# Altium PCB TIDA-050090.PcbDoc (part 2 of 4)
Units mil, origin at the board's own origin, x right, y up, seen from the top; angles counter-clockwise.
Board outline 4150 x 4140 mil, 8 copper layers (Top Layer 1, POWER1, GND1, SIGNAL1, SIGNAL2, GND2, POWER2, Bottom Layer 1), stack 60.703 mil thick; 130 components, 39 nets, 355 pads, 2292 vias.
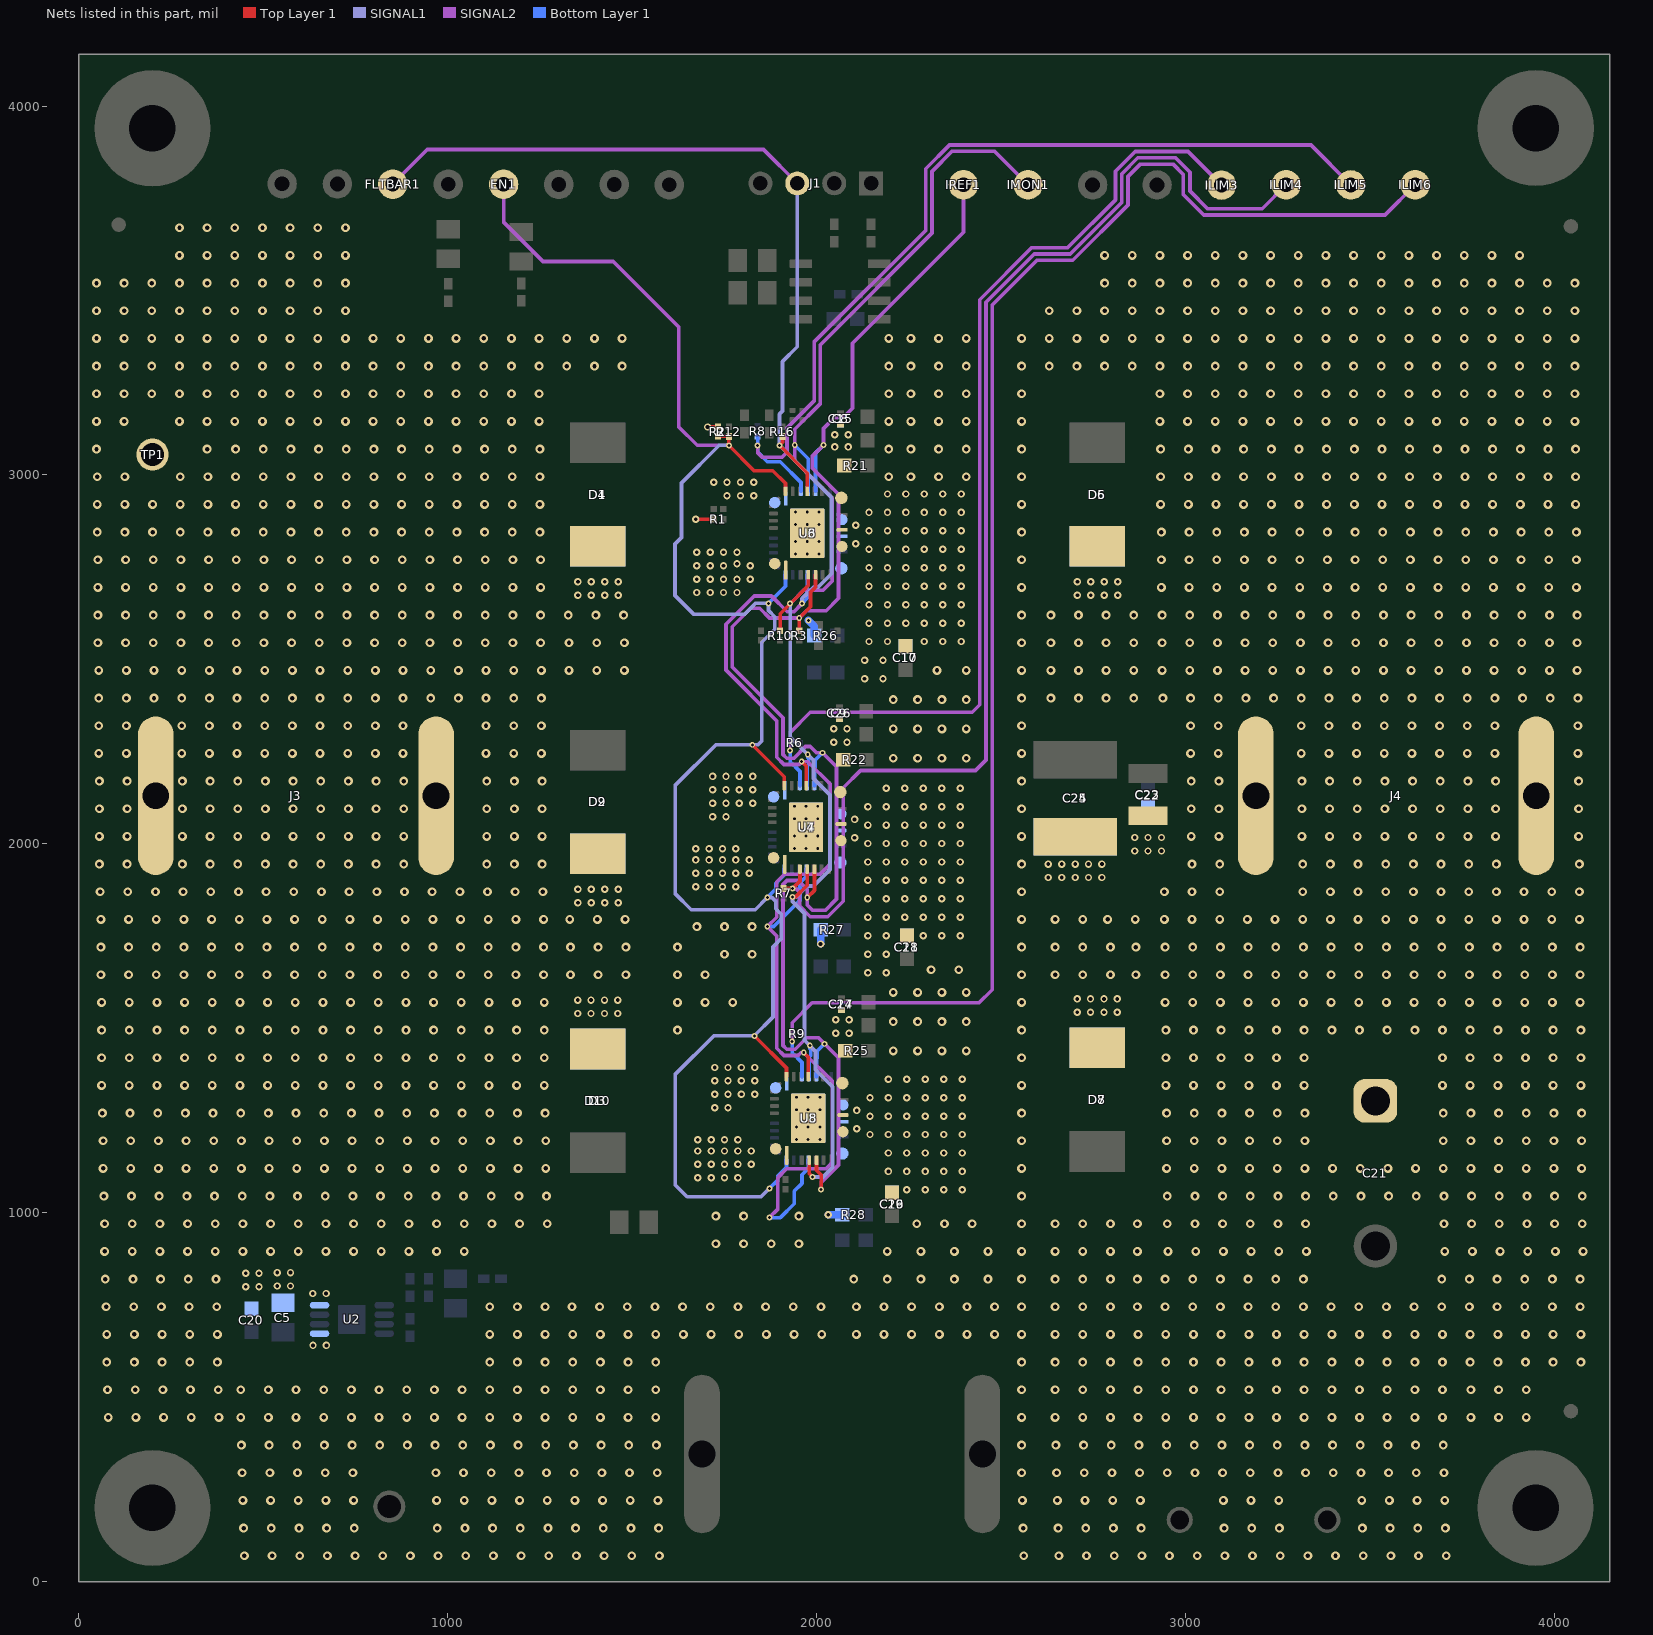
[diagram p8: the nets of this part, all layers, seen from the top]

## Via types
v1: diameter 24, hole 12, Top Layer 1 to Bottom Layer 1, tented both sides, 1740 vias
v2: diameter 20, hole 10, Top Layer 1 to Bottom Layer 1, tented both sides, 444 vias
v3: diameter 16, hole 8, Top Layer 1 to Bottom Layer 1, tented both sides, 67 vias
v4: diameter 19.68, hole 7.87, Top Layer 1 to Bottom Layer 1, tented both sides, 41 vias

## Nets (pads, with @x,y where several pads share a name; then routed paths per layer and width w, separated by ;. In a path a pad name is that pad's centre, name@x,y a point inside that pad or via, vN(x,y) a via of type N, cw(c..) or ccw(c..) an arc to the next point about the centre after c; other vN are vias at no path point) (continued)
Efuse3_ILIM: ILIM3.1 R6.2 U7.1 | length 2723.4
  SIGNAL2 w10: v3(1928.76,2253.39) 1928.76,2302.07 1983.22,2356.53 2422.01,2356.53 2442.44,2376.97 2442.44,3475.39 2583.18,3616.13 2680.82,3616.13 2810.48,3745.79 2810.48,3823.16 2864.07,3876.75 3007.38,3876.75 ILIM3.1@3098.2,3785.94
  Bottom Layer 1 w10: R6.2@1928.76,2273.8 v3(1928.76,2253.39) 1928.76,2222.98 1955.33,2196.4 U7.1@1955.33,2158.19
Efuse4_ILIM: ILIM4.1 R7.2 U4.1 | length 3395.5
  Top Layer 1 w10: R7.2@1911.02,1879.1 v3(1934.93,1879.1) 1955.32,1899.48 U4.1@1955.32,1931.81
  SIGNAL2 w10: v3(1934.93,1879.1) 1944.65,1879.1 1953.93,1869.82 1953.93,1831.64 1982.89,1802.68 2030.63,1802.68 2072.51,1844.56 2072.51,2151.88 2119.68,2199.05 2431.09,2199.05 2459.44,2227.4 2459.44,3468.35 2590.22,3599.13 2687.87,3599.13 2827.48,3738.74 2827.48,3816.12 2871.11,3859.75 2973.32,3859.75 3012.51,3820.57 3012.51,3769.62 3060.17,3721.96 3208.38,3721.96 ILIM4.1@3273.19,3786.77
Efuse5_ILIM: ILIM5.1 R8.2 U6.1 | length 2477.2
  SIGNAL2 w10: v3(1840.51,3080) 1840.51,3061.07 1853.84,3047.73 1906,3047.73 1920.04,3061.77 1920.04,3127.17 1993.63,3200.76 1993.63,3360.44 2295.98,3662.79 2295.98,3830.11 2360.32,3894.45 3340.45,3894.45 ILIM5.1@3448.63,3786.27
  Bottom Layer 1 w10: R8.2@1840.51,3105.46 v3(1840.51,3080) 1840.51,3062.1 1866.65,3035.96 1901.93,3035.96 1958.27,2979.63 U6.1@1958.27,2955.69
Efuse6_ILIM: ILIM6.1 R9.2 U8.1 | length 4085.8
  SIGNAL2 w10: v3(1934.31,1464.45) 1934.31,1515.26 1988.18,1569.13 2440.94,1569.13 2476.44,1604.64 2476.44,3461.06 2597.52,3582.13 2694.91,3582.13 2844.48,3731.7 2844.48,3809.08 2878.15,3842.75 2966.28,3842.75 2993.94,3815.1 2993.94,3761.11 3050.1,3704.96 3541.38,3704.96 ILIM6.1@3623.19,3786.77
  Bottom Layer 1 w10: R9.2@1934.31,1484.86 v3(1934.31,1464.45) 1934.31,1434.04 1960.88,1407.46 U8.1@1960.88,1369.24
Efuse_IN: C5.1 C8.2 C9.2 C14.2 C15.2 C20.1 C26.2 C27.2 D1.1 D2.1 D3.1 D4.1 D9.1 D10.1 J3.1 R1.2 R2.2 R21.2 R22.2 R25.2 R26.2 R27.2 R28.2 TP1.1 U2.5 U2.8 U3.10 U3.22 U3.23 U3.24 U4.10 U4.22 U4.23 U4.24 U5.10 U5.22 U5.23 U5.24 U6.10 U6.22 U6.23 U6.24 U7.10 U7.22 U7.23 U7.24 U8.10 U8.22 U8.23 U8.24 | length 201.7
  Top Layer 1 w10: v2(1672.49,2879.9) R1.2@1721.29,2879.9 ; v2@1704.48,3130.62 R2.2@1732.86,3130.62
  Bottom Layer 1 w20: v3(1977.95,2606.1) 1993.7,2590.36 R26.2@1993.7,2564.86 ; v2(2011.16,1728.61) R27.2@2011.16,1766.96 ; v2(2031.78,994.48) R28.2@2070.13,994.48
  other v1: 449.21,70.29 524.21,70.29 599.21,70.29 674.21,70.29 749.21,70.29 824.21,70.29 899.21,70.29 974.21,70.29 1049.22,70.29 1124.22,70.29 1199.22,70.29 1274.22,70.29 1349.22,70.29 1424.22,70.29 1499.22,70.29 1574.22,70.29 447.21,145.29 522.21,145.29 597.21,145.29 672.21,145.29 747.21,145.29 972.22,145.29 1047.22,145.29 1122.22,145.29 1197.22,145.29 1272.22,145.29 1347.22,145.29 1422.22,145.29 1497.22,145.29 1572.22,145.29 445.21,220.29 520.21,220.29 595.21,220.29 670.21,220.29 745.21,220.29 970.22,220.29 1045.22,220.29 1120.22,220.29 1195.22,220.29 1270.22,220.29 1345.22,220.29 1420.22,220.29 1495.22,220.29 1570.22,220.29 443.21,295.29 518.21,295.29 593.21,295.29 668.21,295.29 743.21,295.29 968.22,295.29 1043.22,295.29 1118.22,295.29 1193.22,295.29 1268.22,295.29 1343.22,295.29 1418.22,295.3 1493.22,295.3 1568.22,295.3 441.21,370.3 516.21,370.3 591.21,370.3 666.21,370.3 741.21,370.3 816.22,370.3 891.22,370.3 966.22,370.3 1041.22,370.3 1116.22,370.3 1191.22,370.3 1266.22,370.3 1341.22,370.3 1416.22,370.3 1491.22,370.3 1566.22,370.3 80.2,445.28 155.2,445.28 230.21,445.28 305.21,445.28 380.21,445.28 439.21,445.3 514.21,445.3 589.21,445.3 664.21,445.3 739.22,445.3 814.22,445.3 889.22,445.3 964.22,445.3 1039.22,445.3 1114.22,445.3 1189.22,445.3 1264.22,445.3 1339.22,445.3 1414.22,445.3 1489.22,445.3 1564.22,445.3 78.2,520.29 153.21,520.29 228.21,520.29 303.21,520.29 378.21,520.29 439.21,520.3 514.21,520.3 589.21,520.3 664.21,520.3 739.22,520.3 814.22,520.3 889.22,520.3 964.22,520.3 1039.22,520.3 1114.22,520.3 1189.22,520.3 1264.22,520.3 1339.22,520.3 1414.22,520.3 1489.22,520.3 1564.22,520.3 76.21,595.29 151.21,595.29 226.21,595.29 301.21,595.29 376.21,595.29 1114.22,595.3 1189.22,595.3 1264.22,595.3 1339.22,595.3 1414.22,595.3 1489.22,595.3 1564.22,595.3 76.21,670.29 151.21,670.29 226.21,670.29 301.21,670.29 376.21,670.29 1114.22,670.3 1189.22,670.3 1264.22,670.3 1339.22,670.3 1414.22,670.3 1489.22,670.3 1564.22,670.3 1639.22,670.3 1714.23,670.3 1789.23,670.3 1864.23,670.3 1939.23,670.3 2014.23,670.3 74.21,745.29 149.21,745.29 224.21,745.29 299.21,745.29 374.21,745.29 1114.22,745.3 1189.22,745.3 1264.22,745.3 1337.22,745.3 1412.22,745.3 1487.22,745.3 1562.22,745.3 1637.23,745.3 1712.23,745.3 1787.23,745.3 1862.23,745.3 1937.23,745.3 2012.23,745.3 72.21,820.29 147.21,820.29 222.21,820.29 297.21,820.29 372.21,820.29 70.21,895.29 145.21,895.29 220.21,895.29 295.21,895.29 370.21,895.29 445.21,895.29 520.21,895.29 595.21,895.29 670.21,895.29 745.21,895.29 820.22,895.29 895.22,895.29 970.22,895.29 1045.22,895.29 1727.54,915.97 1802.54,915.97 1877.54,915.97 1952.54,915.97 70.21,970.29 145.21,970.29 220.21,970.29 295.21,970.29 370.21,970.29 445.21,970.29 520.21,970.29 595.21,970.29 670.21,970.29 745.21,970.29 820.22,970.29 895.22,970.29 970.22,970.29 1045.22,970.29 1120.22,970.29 1195.22,970.29 1270.22,970.29 1727.54,990.97 1802.54,990.97 1952.54,990.97 68.21,1045.29 143.21,1045.29 218.21,1045.29 293.21,1045.29 368.21,1045.29 443.21,1045.29 518.21,1045.29 593.21,1045.29 668.21,1045.3 743.21,1045.3 818.22,1045.3 893.22,1045.3 968.22,1045.3 1043.22,1045.3 1118.22,1045.3 1193.22,1045.3 1268.22,1045.3 66.21,1120.3 141.21,1120.3 216.21,1120.3 291.21,1120.3 366.21,1120.3 441.21,1120.3 516.21,1120.3 591.21,1120.3 666.21,1120.3 741.22,1120.3 816.22,1120.3 891.22,1120.3 966.22,1120.3 1041.22,1120.3 1116.22,1120.3 1191.22,1120.3 1266.22,1120.3 66.21,1195.3 141.21,1195.3 216.21,1195.3 291.21,1195.3 366.21,1195.3 441.21,1195.3 516.21,1195.3 591.21,1195.3 666.21,1195.3 741.22,1195.3 816.22,1195.3 891.22,1195.3 966.22,1195.3 1041.22,1195.3 1116.22,1195.3 1191.22,1195.3 1266.22,1195.3 64.21,1270.3 139.21,1270.3 214.21,1270.3 289.21,1270.3 364.21,1270.3 439.21,1270.3 514.21,1270.3 589.21,1270.3 664.22,1270.3 739.22,1270.3 814.22,1270.3 889.22,1270.3 964.22,1270.3 1039.22,1270.3 1114.22,1270.3 1189.22,1270.3 1264.22,1270.3 62.21,1345.3 137.21,1345.3 212.21,1345.3 287.21,1345.3 362.21,1345.3 437.21,1345.3 512.21,1345.3 587.22,1345.3 662.22,1345.3 737.22,1345.3 812.22,1345.3 887.22,1345.3 962.22,1345.3 1037.22,1345.3 1112.22,1345.3 1187.22,1345.3 1262.22,1345.3 62.21,1420.3 137.21,1420.3 212.21,1420.3 287.21,1420.3 362.21,1420.3 437.21,1420.3 512.21,1420.3 587.22,1420.3 662.22,1420.3 737.22,1420.3 812.22,1420.3 887.22,1420.3 962.22,1420.3 1037.22,1420.3 1112.22,1420.3 1187.22,1420.3 1262.22,1420.3 62.21,1495.3 137.21,1495.3 212.21,1495.3 287.21,1495.3 362.21,1495.3 437.21,1495.3 512.21,1495.3 587.22,1495.3 662.22,1495.3 737.22,1495.3 812.22,1495.3 887.22,1495.3 962.22,1495.3 1037.22,1495.3 1112.22,1495.3 1187.22,1495.3 1262.22,1495.3 1623.23,1495.31 62.21,1570.3 137.21,1570.3 212.21,1570.3 287.21,1570.3 362.21,1570.3 437.21,1570.3 512.21,1570.3 587.22,1570.3 662.22,1570.3 737.22,1570.3 812.22,1570.3 887.22,1570.3 962.22,1570.3 1037.22,1570.3 1112.22,1570.3 1187.22,1570.3 1262.22,1570.3 1623.23,1570.31 1698.23,1570.31 1773.23,1570.31 60.21,1645.3 135.21,1645.3 210.21,1645.3 285.21,1645.3 360.21,1645.3 435.21,1645.3 510.22,1645.3 585.22,1645.3 660.22,1645.3 735.22,1645.3 810.22,1645.3 885.22,1645.3 960.22,1645.3 1035.22,1645.3 1110.22,1645.3 1185.22,1645.3 1260.22,1645.3 1333.22,1645.3 1408.23,1645.3 1483.23,1645.3 1623.23,1645.31 1698.23,1645.31 1750.73,1700.82 1825.73,1700.82 60.21,1720.3 135.21,1720.3 210.21,1720.3 285.21,1720.3 360.21,1720.3 435.21,1720.3 510.22,1720.3 585.22,1720.3 660.22,1720.3 735.22,1720.3 810.22,1720.3 885.22,1720.3 960.22,1720.3 1035.22,1720.3 1110.22,1720.3 1185.22,1720.3 1260.22,1720.3 1333.22,1720.3 1408.23,1720.3 1483.23,1720.3 1623.23,1720.32 1675.73,1775.82 1750.73,1775.82 1825.73,1775.82 60.21,1795.3 135.21,1795.3 210.21,1795.3 285.21,1795.3 360.21,1795.3 435.21,1795.3 510.22,1795.3 585.22,1795.3 660.22,1795.3 735.22,1795.3 810.22,1795.3 885.22,1795.3 960.22,1795.3 1035.22,1795.3 1110.22,1795.3 1185.22,1795.3 1260.22,1795.3 1331.23,1795.31 1406.23,1795.31 1481.23,1795.31 58.21,1870.3 133.21,1870.3 208.21,1870.3 283.21,1870.3 358.21,1870.3 433.22,1870.3 508.22,1870.3 583.22,1870.3 658.22,1870.3 733.22,1870.3 808.22,1870.3 883.22,1870.3 958.22,1870.3 1033.22,1870.3 1108.22,1870.3 1183.22,1870.3 1258.22,1870.3 56.21,1945.3 131.21,1945.3 281.21,1945.3 356.22,1945.3 431.22,1945.3 506.22,1945.3 581.22,1945.31 656.22,1945.31 731.22,1945.31 806.22,1945.31 881.22,1945.31 1106.22,1945.31 1181.22,1945.31 1256.22,1945.31 56.21,2020.3 131.21,2020.3 281.21,2020.3 356.22,2020.3 431.22,2020.3 506.22,2020.31 581.22,2020.31 656.22,2020.31 731.22,2020.31 806.22,2020.31 881.22,2020.31 1106.22,2020.31 1181.22,2020.31 1256.22,2020.31 56.21,2095.3 131.21,2095.3 281.21,2095.3 356.22,2095.3 431.22,2095.31 506.22,2095.31 581.22,2095.31 656.22,2095.31 731.22,2095.31 806.22,2095.31 881.22,2095.31 1106.22,2095.31 1181.22,2095.31 1256.22,2095.31 56.21,2170.3 131.21,2170.3 281.21,2170.3 356.22,2170.31 431.22,2170.31 506.22,2170.31 581.22,2170.31 656.22,2170.31 731.22,2170.31 806.22,2170.31 881.22,2170.31 1106.22,2170.31 1181.22,2170.31 1256.22,2170.31 54.21,2245.31 129.21,2245.31 279.22,2245.31 354.22,2245.31 429.22,2245.31 504.22,2245.31 579.22,2245.31 654.22,2245.31 729.22,2245.31 804.22,2245.31 879.22,2245.31 1104.22,2245.31 1179.22,2245.31 1254.23,2245.31 54.21,2320.31 129.21,2320.31 279.22,2320.31 354.22,2320.31 429.22,2320.31 504.22,2320.31 579.22,2320.31 654.22,2320.31 729.22,2320.31 804.22,2320.31 879.22,2320.31 1104.22,2320.31 1179.22,2320.31 1254.23,2320.31 54.21,2395.31 129.21,2395.31 204.21,2395.31 279.22,2395.31 354.22,2395.31 429.22,2395.31 504.22,2395.31 579.22,2395.31 654.22,2395.31 729.22,2395.31 804.22,2395.31 879.22,2395.31 954.22,2395.31 1029.22,2395.31 1104.22,2395.31 1179.22,2395.31 1254.23,2395.31 54.21,2470.31 129.21,2470.31 204.21,2470.31 279.22,2470.31 354.22,2470.31 429.22,2470.31 504.22,2470.31 579.22,2470.31 654.22,2470.31 729.22,2470.31 804.22,2470.31 879.22,2470.31 954.22,2470.31 1029.22,2470.31 1104.22,2470.31 1179.22,2470.31 1254.23,2470.31 1329.23,2470.31 1404.23,2470.31 1479.23,2470.31 52.21,2545.31 127.21,2545.31 202.22,2545.31 277.22,2545.31 352.22,2545.31 427.22,2545.31 502.22,2545.31 577.22,2545.31 652.22,2545.31 727.22,2545.31 802.22,2545.31 877.22,2545.31 952.22,2545.31 1027.22,2545.31 1102.22,2545.31 1177.23,2545.31 1252.23,2545.31 1329.23,2545.31 1404.23,2545.31 1479.23,2545.31 52.21,2620.31 127.21,2620.31 202.22,2620.31 277.22,2620.31 352.22,2620.31 427.22,2620.31 502.22,2620.31 577.22,2620.31 652.22,2620.31 727.22,2620.31 802.22,2620.31 877.22,2620.31 952.22,2620.31 1027.22,2620.31 1102.22,2620.31 1177.23,2620.31 1252.23,2620.31 1327.23,2620.31 1402.23,2620.31 1477.23,2620.31 52.21,2695.31 127.21,2695.31 202.22,2695.31 277.22,2695.31 352.22,2695.31 427.22,2695.31 502.22,2695.31 577.22,2695.31 652.22,2695.31 727.22,2695.31 802.22,2695.31 877.22,2695.31 952.22,2695.31 1027.22,2695.31 1102.23,2695.31 1177.23,2695.31 1252.23,2695.31 52.21,2770.31 127.21,2770.31 202.22,2770.31 277.22,2770.31 352.22,2770.31 427.22,2770.31 502.22,2770.31 577.22,2770.31 652.22,2770.31 727.22,2770.31 802.22,2770.31 877.22,2770.31 952.22,2770.31 1027.22,2770.31 1102.23,2770.31 1177.23,2770.31 1252.23,2770.31 50.21,2845.31 125.22,2845.31 200.22,2845.31 275.22,2845.31 350.22,2845.31 425.22,2845.31 500.22,2845.31 575.22,2845.31 650.22,2845.31 725.22,2845.31 800.22,2845.31 875.22,2845.31 950.22,2845.31 1025.22,2845.31 1100.23,2845.31 1175.23,2845.31 1250.23,2845.31 50.21,2920.31 125.22,2920.31 200.22,2920.31 275.22,2920.31 350.22,2920.31 425.22,2920.31 500.22,2920.31 575.22,2920.31 650.22,2920.31 725.22,2920.31 800.22,2920.31 875.22,2920.31 950.22,2920.31 1025.23,2920.31 1100.23,2920.31 1175.23,2920.31 1250.23,2920.31 50.21,2995.31 125.22,2995.31 275.22,2995.31 350.22,2995.31 425.22,2995.31 500.22,2995.31 575.22,2995.31 650.22,2995.31 725.22,2995.31 800.22,2995.31 875.22,2995.31 950.22,2995.31 1025.23,2995.31 1100.23,2995.31 1175.23,2995.31 1250.23,2995.31 48.22,3070.31 348.22,3070.31 425.22,3070.31 500.22,3070.31 575.22,3070.31 650.22,3070.31 725.22,3070.31 800.22,3070.31 875.22,3070.31 950.22,3070.31 1025.23,3070.31 1100.23,3070.31 1175.23,3070.31 1250.23,3070.31 48.22,3145.31 123.22,3145.31 273.22,3145.31 348.22,3145.31 423.22,3145.31 498.22,3145.31 573.22,3145.31 648.22,3145.31 723.22,3145.31 798.22,3145.31 873.22,3145.31 948.23,3145.31 1023.23,3145.31 1098.23,3145.31 1173.23,3145.31 1248.23,3145.31 48.22,3220.31 123.22,3220.31 198.22,3220.31 273.22,3220.31 348.22,3220.31 423.22,3220.31 498.22,3220.31 573.22,3220.31 648.22,3220.31 723.22,3220.31 798.22,3220.31 873.22,3220.31 948.23,3220.31 1023.23,3220.31 1098.23,3220.31 1173.23,3220.31 1248.23,3220.31 48.22,3295.31 123.22,3295.31 198.22,3295.31 273.22,3295.31 348.22,3295.31 423.22,3295.31 498.22,3295.31 573.22,3295.31 648.22,3295.31 723.22,3295.31 798.22,3295.31 873.22,3295.31 948.23,3295.31 1023.23,3295.31 1098.23,3295.31 1173.23,3295.31 1248.23,3295.31 1323.23,3295.31 1398.23,3295.31 1473.23,3295.31 48.22,3370.31 123.22,3370.31 198.22,3370.31 273.22,3370.31 348.22,3370.31 423.22,3370.31 498.22,3370.31 573.22,3370.31 648.22,3370.31 723.22,3370.31 798.22,3370.31 873.22,3370.31 948.23,3370.31 1023.23,3370.31 1098.23,3370.31 1173.23,3370.31 1248.23,3370.31 1323.23,3370.31 1398.23,3370.31 1473.23,3370.31 48.22,3445.31 123.22,3445.31 198.22,3445.31 273.22,3445.31 348.22,3445.31 423.22,3445.31 498.22,3445.31 573.22,3445.31 648.22,3445.31 723.22,3445.31 48.22,3520.31 123.22,3520.31 198.22,3520.31 273.22,3520.31 348.22,3520.31 423.22,3520.31 498.22,3520.31 573.22,3520.31 648.22,3520.31 723.22,3520.31 273.22,3595.31 348.22,3595.31 423.22,3595.31 498.22,3595.31 573.22,3595.31 648.22,3595.31 723.22,3595.31 273.22,3670.31 348.22,3670.31 423.22,3670.31 498.22,3670.31 573.22,3670.31 648.22,3670.31 723.22,3670.31
  other v2: 635.23,640.41 671.57,640.41 634.31,781.31 670.66,781.31 452.63,799.86 488.97,799.86 537.91,801.54 574.25,801.54 452.63,836.21 488.97,836.21 537.91,837.88 574.25,837.88 1678.07,1094.91 1714.42,1094.91 1750.76,1094.91 1787.11,1094.91 1678.07,1131.26 1714.42,1131.26 1750.76,1131.26 1787.11,1131.26 1823.46,1131.26 1678.07,1167.6 1714.42,1167.6 1750.76,1167.6 1787.11,1167.6 1823.46,1167.6 1678.07,1198.18 1714.42,1198.18 1750.76,1198.18 1787.11,1198.18 1723.91,1284.92 1760.25,1284.92 1723.91,1321.27 1760.25,1321.27 1796.6,1321.27 1832.94,1321.27 1723.91,1357.62 1760.25,1357.62 1796.6,1357.62 1832.94,1357.62 1723.91,1393.96 1760.25,1393.96 1796.6,1393.96 1832.94,1393.96 2052.11,1486.7 2088.46,1486.7 2052.11,1523.04 2088.46,1523.04 1352.58,1540.24 1388.93,1540.24 1425.28,1540.24 1461.62,1540.24 1352.58,1576.58 1388.93,1576.58 1425.28,1576.58 1461.62,1576.58 1353.32,1840.7 1389.67,1840.7 1426.01,1840.7 1462.36,1840.7 1353.32,1877.05 1389.67,1877.05 1426.01,1877.05 1462.36,1877.05 1672.52,1883.86 1708.87,1883.86 1745.21,1883.86 1781.56,1883.86 1672.52,1920.2 1708.87,1920.2 1745.21,1920.2 1781.56,1920.2 1817.9,1920.2 1672.52,1956.55 1708.87,1956.55 1745.21,1956.55 1781.56,1956.55 1817.9,1956.55 1672.52,1987.12 1708.87,1987.12 1745.21,1987.12 1781.56,1987.12 1718.35,2073.87 1754.7,2073.87 1718.35,2110.21 1754.7,2110.21 1791.05,2110.21 1827.39,2110.21 1718.35,2146.56 1754.7,2146.56 1791.05,2146.56 1827.39,2146.56 1718.35,2182.91 1754.7,2182.91 1791.05,2182.91 1827.39,2182.91 2046.54,2275.64 2082.89,2275.64 2046.54,2311.99 2082.89,2311.99 1353.32,2673.89 1389.67,2673.89 1426.01,2673.89 1462.36,2673.89 1675.47,2681.36 1711.82,2681.36 1748.16,2681.36 1784.51,2681.36 1353.32,2710.23 1389.67,2710.23 1426.01,2710.23 1462.36,2710.23 1675.47,2717.7 1711.82,2717.7 1748.16,2717.7 1784.51,2717.7 1820.86,2717.7 1675.47,2754.05 1711.82,2754.05 1748.16,2754.05 1820.86,2754.05 1784.51,2759.82 1675.47,2790.39 1711.82,2790.39 1748.16,2790.39 1784.51,2790.39 1757.64,2944.06 1793.98,2944.06 1830.33,2944.06 1721.29,2980.41 1757.64,2980.41 1793.98,2980.41 1830.33,2980.41 2049.5,3076.14 2085.84,3076.14 2049.5,3109.49 2085.84,3109.49 1704.83,3130.27
  other v4: 1946.12,1198.97 1977.62,1198.97 2009.11,1198.97 1946.12,1232.83 1977.62,1232.83 2009.11,1232.83 1946.12,1279.28 1977.62,1279.28 2009.11,1279.28 1946.12,1313.14 1977.62,1313.14 2009.11,1313.14 1940.57,1987.91 1972.06,1987.91 2003.56,1987.91 1940.57,2021.77 1972.06,2021.77 2003.56,2021.77 1940.57,2068.23 1972.06,2068.23 2003.56,2068.23 1940.57,2102.09 1972.06,2102.09 2003.56,2102.09 1943.5,2785.41 1975,2785.41 2006.5,2785.41 1943.5,2819.27 1975,2819.27 2006.5,2819.27 1943.5,2865.73 1975,2865.73 2006.5,2865.73 1943.5,2899.59 1975,2899.59 2006.5,2899.59
Efuse_OUT: C10.1 C11.1 C16.1 C17.1 C21.1 C22.2 C23.2 C24.1 C25.1 C28.1 C29.1 D5.1 D6.1 D7.1 D8.1 J4.1 U3.7 U3.8 U4.7 U4.8 U5.7 U5.8 U6.7 U6.8 U7.7 U7.8 U8.7 U8.8
  other v1: 2562.08,70.29 2657.07,70.29 2732.07,70.29 2807.07,70.29 2882.07,70.29 2957.07,70.29 3032.07,70.29 3107.08,70.29 3182.08,70.29 3257.08,70.29 3332.08,70.29 3407.08,70.29 3482.08,70.29 3557.08,70.29 3632.08,70.29 3707.08,70.29 2560.08,145.29 2655.07,145.29 2730.07,145.29 2805.07,145.29 2880.07,145.29 3105.08,145.29 3180.08,145.29 3255.08,145.29 3480.08,145.29 3555.08,145.29 3630.08,145.29 3705.08,145.29 2558.08,220.29 2653.07,220.29 2728.07,220.29 2803.07,220.29 2878.07,220.29 3103.08,220.29 3178.08,220.29 3253.08,220.29 3478.08,220.29 3553.08,220.29 3628.08,220.29 3703.08,220.29 2556.08,295.29 2651.07,295.29 2726.07,295.29 2801.07,295.29 2876.07,295.29 2951.08,295.29 3026.08,295.29 3101.08,295.29 3176.08,295.29 3251.08,295.29 3326.08,295.29 3401.08,295.29 3476.08,295.29 3551.08,295.29 3626.08,295.29 3701.08,295.29 2556.08,370.29 2649.07,370.3 2724.07,370.3 2799.07,370.3 2874.08,370.3 2949.08,370.3 3024.08,370.3 3099.08,370.3 3174.08,370.3 3249.08,370.3 3324.08,370.3 3399.08,370.3 3474.08,370.3 3549.08,370.3 3624.08,370.3 3699.08,370.3 2556.08,445.3 2647.07,445.3 2722.07,445.3 2797.08,445.3 2872.08,445.3 2947.08,445.3 3022.08,445.3 3097.08,445.3 3172.08,445.3 3247.08,445.3 3322.08,445.3 3397.08,445.3 3472.08,445.3 3547.08,445.3 3622.08,445.3 3697.08,445.3 3774.09,445.3 3849.09,445.3 3924.09,445.3 2556.08,520.3 2647.07,520.3 2722.07,520.3 2797.08,520.3 2872.08,520.3 2947.08,520.3 3022.08,520.3 3097.08,520.3 3172.08,520.3 3247.08,520.3 3322.08,520.3 3397.08,520.3 3472.08,520.3 3547.08,520.3 3622.08,520.3 3697.09,520.3 3774.09,520.3 3849.09,520.3 3924.09,520.3 2556.08,595.3 2647.07,595.3 2722.07,595.3 2797.08,595.3 2872.08,595.3 2947.08,595.3 3022.08,595.3 3097.08,595.3 3172.08,595.3 3247.08,595.3 3322.08,595.3 3397.08,595.3 3472.08,595.3 3547.08,595.3 3622.08,595.3 3697.09,595.3 3772.09,595.3 3847.09,595.3 3922.09,595.3 3997.09,595.3 4072.09,595.3 2108.07,670.29 2183.07,670.29 2258.07,670.29 2333.07,670.3 2408.08,670.3 2483.08,670.3 2556.08,670.3 2647.07,670.3 2722.07,670.3 2797.08,670.3 2872.08,670.3 2947.08,670.3 3022.08,670.3 3097.08,670.3 3172.08,670.3 3247.08,670.3 3322.08,670.3 3397.08,670.3 3472.08,670.3 3547.08,670.3 3622.08,670.3 3697.09,670.3 3772.09,670.3 3847.09,670.3 3922.09,670.3 3997.09,670.3 4072.09,670.3 2108.07,745.29 2183.07,745.29 2258.07,745.3 2333.07,745.3 2408.08,745.3 2483.08,745.3 2556.08,745.3 2647.07,745.3 2722.07,745.3 2797.08,745.3 2870.08,745.3 2945.08,745.3 3020.08,745.3 3095.08,745.3 3170.08,745.3 3245.08,745.3 3320.08,745.3 3395.08,745.3 3470.08,745.3 3545.08,745.3 3620.09,745.3 3695.09,745.3 3770.09,745.3 3845.09,745.3 3920.09,745.3 3995.09,745.3 4070.09,745.3 2101.09,820.3 2192.09,820.3 2283.09,820.3 2374.08,820.3 2465.08,820.3 2556.08,820.3 2647.07,820.3 2722.08,820.3 2797.08,820.3 2870.08,820.3 2945.08,820.3 3020.08,820.3 3095.08,820.3 3170.08,820.3 3245.08,820.3 3320.08,820.3 3695.09,820.3 3770.09,820.3 3845.09,820.3 3920.09,820.3 3995.09,820.3 4070.09,820.3 2192.09,895.3 2283.09,895.3 2374.08,895.3 2465.08,895.3 2556.08,895.3 2647.07,895.3 2722.08,895.3 2797.08,895.3 2870.08,895.3 2953.08,895.3 3028.08,895.3 3103.08,895.3 3178.08,895.3 3253.08,895.3 3328.08,895.3 3703.08,895.3 3778.08,895.3 3853.09,895.3 3928.09,895.3 4003.09,895.3 4078.09,895.3 2272.07,970.3 2347.07,970.29 2422.07,970.29 2556.08,970.29 2647.07,970.29 2722.08,970.29 2797.08,970.29 2870.08,970.29 2951.08,970.29 3026.08,970.29 3101.08,970.29 3176.08,970.29 3251.08,970.29 3326.08,970.29 3701.08,970.29 3776.09,970.29 3851.09,970.29 3926.09,970.29 4001.09,970.29 4076.09,970.29 2556.08,1045.31 2951.08,1045.29 3026.08,1045.29 3101.08,1045.3 3176.08,1045.3 3251.08,1045.3 3326.08,1045.3 3401.08,1045.3 3476.08,1045.3 3551.08,1045.3 3626.08,1045.3 3701.08,1045.3 3776.09,1045.3 3851.09,1045.3 3926.09,1045.3 4001.09,1045.3 4076.09,1045.3 2556.08,1120.31 2949.08,1120.3 3024.08,1120.3 3099.08,1120.3 3174.08,1120.3 3249.08,1120.3 3324.08,1120.3 3399.08,1120.3 3474.08,1120.3 3549.08,1120.3 3624.08,1120.3 3699.09,1120.3 3774.09,1120.3 3849.09,1120.3 3924.09,1120.3 3999.09,1120.3 4074.09,1120.3 2556.08,1195.31 2949.08,1195.3 3024.08,1195.3 3099.08,1195.3 3174.08,1195.3 3249.08,1195.3 3324.08,1195.3 3699.09,1195.3 3774.09,1195.3 3849.09,1195.3 3924.09,1195.3 3999.09,1195.3 4074.09,1195.3 2556.08,1270.31 2949.08,1270.3 3024.08,1270.3 3099.08,1270.3 3174.08,1270.3 3249.08,1270.3 3324.08,1270.3 3699.09,1270.3 3774.09,1270.3 3849.09,1270.3 3924.09,1270.3 3999.09,1270.3 4074.09,1270.3 2556.08,1345.31 2947.08,1345.3 3022.08,1345.3 3097.08,1345.3 3172.08,1345.3 3247.08,1345.3 3322.08,1345.3 3697.09,1345.3 3772.09,1345.3 3847.09,1345.3 3922.09,1345.3 3997.09,1345.3 4072.09,1345.3 2556.08,1420.31 2947.08,1420.3 3022.08,1420.3 3097.08,1420.3 3172.08,1420.3 3247.08,1420.3 3322.08,1420.3 3697.09,1420.3 3772.09,1420.3 3847.09,1420.3 3922.09,1420.3 3997.09,1420.3 4072.09,1420.3 2208.04,1438.84 2274.05,1438.83 2340.06,1438.83 2406.08,1438.83 2556.08,1495.31 2947.08,1495.3 3022.08,1495.3 3097.08,1495.3 3172.08,1495.3 3247.08,1495.3 3322.08,1495.3 3397.08,1495.3 3472.08,1495.3 3547.08,1495.3 3622.09,1495.3 3697.09,1495.3 3772.09,1495.3 3847.09,1495.3 3922.09,1495.3 3997.09,1495.3 4072.09,1495.3 2208.04,1518.18 2274.05,1518.18 2340.06,1518.17 2406.08,1518.17 2556.08,1570.31 2945.08,1570.3 3020.08,1570.3 3095.08,1570.3 3170.08,1570.3 3245.08,1570.3 3320.08,1570.3 3395.08,1570.3 3470.08,1570.3 3545.09,1570.3 3620.09,1570.3 3695.09,1570.3 3770.09,1570.3 3845.09,1570.3 3920.09,1570.3 3995.09,1570.3 4070.09,1570.3 2208.04,1597.52 2274.05,1597.52 2340.06,1597.52 2406.08,1597.52 2556.08,1645.31 2647.08,1645.3 2722.08,1645.3 2797.08,1645.3 2866.08,1645.3 2945.08,1645.3 3020.08,1645.3 3095.08,1645.3 3170.08,1645.3 3245.08,1645.3 3320.08,1645.3 3395.08,1645.3 3470.08,1645.3 3545.09,1645.3 3620.09,1645.3 3695.09,1645.3 3770.09,1645.3 3845.09,1645.3 3920.09,1645.3 3995.09,1645.3 4070.09,1645.3 2310.62,1658.7 2385.62,1658.7 2556.08,1720.31 2647.08,1720.3 2722.08,1720.3 2797.08,1720.3 2866.08,1720.3 2945.08,1720.3 3020.08,1720.3 3095.08,1720.3 3170.08,1720.3 3245.08,1720.3 3320.08,1720.3 3395.08,1720.3 3470.08,1720.3 3545.09,1720.3 3620.09,1720.3 3695.09,1720.3 3770.09,1720.3 3845.09,1720.3 3920.09,1720.3 3995.09,1720.3 4070.09,1720.3 2556.08,1795.31 2647.08,1795.3 2722.08,1795.3 2789.08,1795.3 2864.08,1795.3 2943.08,1795.3 3018.08,1795.3 3093.08,1795.3 3168.08,1795.3 3243.08,1795.3 3318.08,1795.3 3393.08,1795.3 3468.09,1795.3 3543.09,1795.3 3618.09,1795.3 3693.09,1795.3 3768.09,1795.3 3843.09,1795.3 3918.09,1795.3 3993.09,1795.3 4068.09,1795.3 2556.08,1870.31 2943.08,1870.3 3018.08,1870.3 3093.08,1870.3 3318.08,1870.3 3393.08,1870.3 3468.09,1870.3 3543.09,1870.3 3618.09,1870.3 3693.09,1870.3 3768.09,1870.3 3843.09,1870.3 3918.09,1870.3 3993.09,1870.3 4068.09,1870.3 2556.08,1945.31 3018.08,1945.3 3093.08,1945.3 3318.08,1945.3 3393.08,1945.3 3468.09,1945.3 3543.09,1945.3 3618.09,1945.3 3693.09,1945.3 3768.09,1945.3 3843.09,1945.3 4068.09,1945.3 2556.08,2020.31 3016.08,2020.3 3091.08,2020.3 3316.08,2020.3 3391.09,2020.3 3466.09,2020.3 3541.09,2020.3 3616.09,2020.3 3691.09,2020.3 3766.09,2020.3 3841.09,2020.3 4066.09,2020.31 2556.08,2095.31 3016.08,2095.3 3091.08,2095.3 3316.08,2095.3 3391.09,2095.3 3466.09,2095.3 3541.09,2095.3 3616.09,2095.3 3691.09,2095.3 3766.09,2095.3 3841.09,2095.3 4066.09,2095.31 2556.08,2170.31 3016.08,2170.3 3091.08,2170.3 3316.08,2170.3 3391.09,2170.3 3466.09,2170.3 3541.09,2170.3 3616.09,2170.3 3691.09,2170.3 3766.09,2170.3 3841.09,2170.3 4066.09,2170.31 2208.04,2232.29 2274.05,2232.28 2340.06,2232.28 2406.08,2232.28 2556.08,2245.31 3014.08,2245.31 3089.08,2245.31 3314.09,2245.31 3389.09,2245.31 3464.09,2245.31 3539.09,2245.31 3614.09,2245.31 3689.09,2245.31 3764.09,2245.31 3839.09,2245.31 4064.09,2245.31 2208.04,2311.63 2274.05,2311.63 2340.06,2311.62 2406.08,2311.62 2556.08,2320.31 3014.08,2320.31 3089.08,2320.31 3314.09,2320.31 3389.09,2320.31 3464.09,2320.31 3539.09,2320.31 3614.09,2320.31 3689.09,2320.31 3764.09,2320.31 3839.09,2320.31 4064.09,2320.31 2208.04,2390.97 2274.05,2390.97 2340.06,2390.97 2406.08,2390.96 2556.08,2395.31 2635.42,2395.31 2710.42,2395.31 2785.08,2395.31 2860.08,2395.31 2939.08,2395.31 3014.08,2395.31 3089.08,2395.31 3164.08,2395.31 3239.08,2395.31 3314.09,2395.31 3389.09,2395.31 3464.09,2395.31 3539.09,2395.31 3614.09,2395.31 3689.09,2395.31 3764.09,2395.31 3839.09,2395.31 3914.09,2395.31 3989.09,2395.31 4064.09,2395.31 2326.73,2470.31 2406.08,2470.31 2556.08,2470.31 2635.42,2470.31 2710.42,2470.31 2785.08,2470.31 2860.08,2470.31 2937.08,2470.31 3012.08,2470.31 3087.08,2470.31 3162.08,2470.31 3237.09,2470.31 3312.09,2470.31 3387.09,2470.31 3462.09,2470.31 3537.09,2470.31 3612.09,2470.31 3687.09,2470.31 3762.09,2470.31 3837.09,2470.31 3912.09,2470.31 3987.09,2470.31 4062.09,2470.31 2556.08,2545.31 2635.42,2545.31 2710.42,2545.31 2785.08,2545.31 2860.08,2545.31 2937.08,2545.31 3012.08,2545.31 3087.08,2545.31 3162.08,2545.31 3237.09,2545.31 3312.09,2545.31 3387.09,2545.31 3462.09,2545.31 3537.09,2545.31 3612.09,2545.31 3687.09,2545.31 3762.09,2545.31 3837.09,2545.31 3912.09,2545.31 3987.09,2545.31 4062.09,2545.31 2556.08,2620.31 2635.42,2620.31 2710.42,2620.31 2785.08,2620.31 2860.08,2620.31 2937.08,2620.31 3012.08,2620.31 3087.08,2620.31 3162.08,2620.31 3237.09,2620.31 3312.09,2620.31 3387.09,2620.31 3462.09,2620.31 3537.09,2620.31 3612.09,2620.31 3687.09,2620.31 3762.09,2620.31 3837.09,2620.31 3912.09,2620.31 3987.09,2620.31 4062.09,2620.31 2556.08,2695.31 2935.08,2695.31 3010.08,2695.31 3085.08,2695.31 3160.09,2695.31 3235.09,2695.31 3310.09,2695.31 3385.09,2695.31 3460.09,2695.31 3535.09,2695.31 3610.09,2695.31 3685.09,2695.31 3760.09,2695.31 3835.09,2695.31 3910.09,2695.31 3985.09,2695.31 4060.09,2695.31 2556.08,2770.31 2935.08,2770.31 3010.08,2770.31 3085.08,2770.31 3160.09,2770.31 3235.09,2770.31 3310.09,2770.31 3385.09,2770.31 3460.09,2770.31 3535.09,2770.31 3610.09,2770.31 3685.09,2770.31 3760.09,2770.31 3835.09,2770.31 3910.09,2770.31 3985.09,2770.31 4060.1,2770.31 2556.08,2845.31 2935.08,2845.31 3010.08,2845.31 3085.08,2845.31 3160.09,2845.31 3235.09,2845.31 3310.09,2845.31 3385.09,2845.31 3460.09,2845.31 3535.09,2845.31 3610.09,2845.31 3685.09,2845.31 3760.09,2845.31 3835.09,2845.31 3910.09,2845.31 3985.09,2845.31 4060.1,2845.31 2556.08,2920.31 2933.08,2920.31 3008.08,2920.31 3083.09,2920.31 3158.09,2920.31 3233.09,2920.31 3308.09,2920.31 3383.09,2920.31 3458.09,2920.31 3533.09,2920.31 3608.09,2920.31 3683.09,2920.31 3758.09,2920.31 3833.09,2920.31 3908.09,2920.31 3983.09,2920.31 4058.1,2920.31 2196.08,2995.31 2256.08,2995.31 2331.08,2995.31 2406.08,2995.31 2556.08,2995.31 2933.08,2995.31 3008.08,2995.31 3083.09,2995.31 3158.09,2995.31 3233.09,2995.31 3308.09,2995.31 3383.09,2995.31 3458.09,2995.31 3533.09,2995.31 3608.09,2995.31 3683.09,2995.31 3758.09,2995.31 3833.09,2995.31 3908.09,2995.31 3983.1,2995.31 4058.1,2995.31 2196.08,3070.31 2256.08,3070.31 2331.08,3070.31 2406.08,3070.31 2556.08,3070.31 2933.08,3070.31 3008.08,3070.31 3083.09,3070.31 3158.09,3070.31 3233.09,3070.31 3308.09,3070.31 3383.09,3070.31 3458.09,3070.31 3533.09,3070.31 3608.09,3070.31 3683.09,3070.31 3758.09,3070.31 3833.09,3070.31 3908.09,3070.31 3983.1,3070.31 4058.1,3070.31 2196.08,3145.31 2256.08,3145.31 2331.08,3145.31 2406.08,3145.31 2556.08,3145.31 2931.08,3145.31 3006.09,3145.31 3081.09,3145.31 3156.09,3145.31 3231.09,3145.31 3306.09,3145.31 3381.09,3145.31 3456.09,3145.31 3531.09,3145.31 3606.09,3145.31 3681.09,3145.31 3756.09,3145.31 3831.09,3145.31 3906.09,3145.31 3981.1,3145.31 4056.1,3145.31 2196.08,3220.31 2256.08,3220.31 2331.08,3220.31 2406.08,3220.31 2556.08,3220.31 2931.08,3220.31 3006.09,3220.31 3081.09,3220.31 3156.09,3220.31 3231.09,3220.31 3306.09,3220.31 3381.09,3220.31 3456.09,3220.31 3531.09,3220.31 3606.09,3220.31 3681.09,3220.31 3756.09,3220.31 3831.09,3220.31 3906.1,3220.31 3981.1,3220.31 4056.1,3220.31 2196.08,3295.31 2256.08,3295.31 2331.08,3295.31 2406.08,3295.31 2556.08,3295.31 2631.08,3295.31 2706.08,3295.31 2781.08,3295.31 2856.08,3295.31 2931.08,3295.31 3006.09,3295.31 3081.09,3295.31 3156.09,3295.31 3231.09,3295.31 3306.09,3295.31 3381.09,3295.31 3456.09,3295.31 3531.09,3295.31 3606.09,3295.31 3681.09,3295.31 3756.09,3295.31 3831.09,3295.31 3906.1,3295.31 3981.1,3295.31 4056.1,3295.31 2196.08,3370.31 2256.08,3370.31 2331.08,3370.31 2406.08,3370.31 2556.08,3370.31 2631.08,3370.31 2706.08,3370.31 2781.08,3370.31 2856.08,3370.31 2931.08,3370.31 3006.09,3370.31 3081.09,3370.31 3156.09,3370.31 3231.09,3370.31 3306.09,3370.31 3381.09,3370.31 3456.09,3370.31 3531.09,3370.31 3606.09,3370.31 3681.09,3370.31 3756.09,3370.31 3831.09,3370.31 3906.1,3370.31 3981.1,3370.31 4056.1,3370.31 2631.08,3445.31 2706.08,3445.31 2781.08,3445.31 2856.08,3445.31 2931.08,3445.31 3006.09,3445.31 3081.09,3445.31 3156.09,3445.31 3231.09,3445.31 3306.09,3445.31 3381.09,3445.31 3456.09,3445.31 3531.09,3445.31 3606.09,3445.31 3681.09,3445.31 3756.09,3445.31 3831.09,3445.31 3906.1,3445.31 3981.1,3445.31 4056.1,3445.31 2781.08,3520.31 2856.08,3520.31 2931.09,3520.31 3006.09,3520.31 3081.09,3520.31 3156.09,3520.31 3231.09,3520.31 3306.09,3520.31 3381.09,3520.31 3456.09,3520.31 3531.09,3520.31 3606.09,3520.31 3681.09,3520.31 3756.09,3520.31 3831.09,3520.31 3906.1,3520.31 3981.1,3520.31 4056.1,3520.31 2781.08,3595.31 2856.08,3595.31 2931.09,3595.31 3006.09,3595.31 3081.09,3595.31 3156.09,3595.31 3231.09,3595.31 3306.09,3595.31 3381.09,3595.31 3456.09,3595.31 3531.09,3595.31 3606.09,3595.31 3681.09,3595.31 3756.09,3595.31 3831.09,3595.31 3906.1,3595.31
  other v2: 2245.11,1062.06 2295.11,1062.06 2345.11,1062.06 2395.11,1062.06 2195.11,1112.06 2245.11,1112.06 2295.11,1112.06 2345.11,1112.06 2395.11,1112.06 2195.11,1162.06 2245.11,1162.06 2295.11,1162.06 2345.11,1162.06 2395.11,1162.06 2145.11,1212.06 2195.11,1212.06 2245.11,1212.06 2295.11,1212.06 2345.11,1212.06 2395.11,1212.06 2108.91,1227.41 2145.11,1262.06 2195.11,1262.06 2245.11,1262.06 2295.11,1262.06 2345.11,1262.06 2395.11,1262.06 2108.91,1277.41 2145.11,1312.06 2195.11,1312.06 2245.11,1312.06 2295.11,1312.06 2345.11,1312.06 2395.11,1312.06 2195.11,1362.06 2245.11,1362.06 2295.11,1362.06 2345.11,1362.06 2395.11,1362.06 2706.65,1543.41 2743,1543.41 2779.35,1543.41 2815.69,1543.41 2706.65,1579.75 2743,1579.75 2779.35,1579.75 2815.69,1579.75 2139.54,1651 2189.54,1651 2139.54,1701 2189.54,1701 2139.54,1751 2189.54,1751 2289.54,1751 2339.54,1751 2389.54,1751 2139.54,1801 2189.54,1801 2239.54,1801 2289.54,1801 2339.54,1801 2389.54,1801 2139.54,1851 2189.54,1851 2239.54,1851 2289.54,1851 2339.54,1851 2389.54,1851 2139.54,1901 2189.54,1901 2239.54,1901 2289.54,1901 2339.54,1901 2389.54,1901 2628.47,1908.89 2664.82,1908.89 2701.16,1908.89 2737.51,1908.89 2773.86,1908.89 2628.47,1945.24 2664.82,1945.24 2701.16,1945.24 2737.51,1945.24 2773.86,1945.24 2139.54,1951 2189.54,1951 2239.54,1951 2289.54,1951 2339.54,1951 2389.54,1951 2862.52,1980.81 2898.87,1980.81 2935.21,1980.81 2139.54,2001 2189.54,2001 2239.54,2001 2289.54,2001 2339.54,2001 2389.54,2001 2103.34,2016.36 2862.52,2017.16 2898.87,2017.16 2935.21,2017.16 2139.54,2051 2189.54,2051 2239.54,2051 2289.54,2051 2339.54,2051 2389.54,2051 2103.34,2066.36 2139.54,2101 2189.54,2101 2239.54,2101 2289.54,2101 2339.54,2101 2389.54,2101 2189.54,2151 2239.54,2151 2289.54,2151 2339.54,2151 2389.54,2151 2130.47,2447.51 2180.47,2447.51 2130.47,2497.51 2180.47,2497.51 2142.49,2548.5 2192.49,2548.5 2292.49,2548.5 2342.49,2548.5 2392.49,2548.5 2142.49,2598.5 2192.49,2598.5 2242.49,2598.5 2292.49,2598.5 2342.49,2598.5 2392.49,2598.5 2142.49,2648.5 2192.49,2648.5 2242.49,2648.5 2292.49,2648.5 2342.49,2648.5 2392.49,2648.5 2707.41,2673.89 2743.75,2673.89 2780.1,2673.89 2816.44,2673.89 2142.49,2698.5 2192.49,2698.5 2242.49,2698.5 2292.49,2698.5 2342.49,2698.5 2392.49,2698.5 2707.41,2710.23 2743.75,2710.23 2780.1,2710.23 2816.44,2710.23 2142.49,2748.5 2192.49,2748.5 2242.49,2748.5 2292.49,2748.5 2342.49,2748.5 2392.49,2748.5 2142.49,2798.5 2192.49,2798.5 2242.49,2798.5 2292.49,2798.5 2342.49,2798.5 2392.49,2798.5 2106.29,2813.86 2142.49,2848.5 2192.49,2848.5 2242.49,2848.5 2292.49,2848.5 2342.49,2848.5 2392.49,2848.5 2106.29,2863.86 2142.49,2898.5 2192.49,2898.5 2242.49,2898.5 2292.49,2898.5 2342.49,2898.5 2392.49,2898.5 2192.49,2948.5 2242.49,2948.5 2292.49,2948.5 2342.49,2948.5 2392.49,2948.5
EN: EN1.1 R2.1 R12.2 U3.16 U4.16 U5.16 U6.16 U7.16 U8.16 | length 5262.5
  Top Layer 1 w10: R2.1@1732.86,3104.64 R12.2@1762.39,3104.6 R12.2@1762.39,3104.6 v3(1762.39,3080.35) 1830.93,3011.81 1881.59,3011.81 1915.94,2977.45 U3.16@1915.94,2955.69 ; v3(1826.01,2268.67) 1912.99,2181.69 U4.16@1912.99,2158.19 ; v3(1831.58,1479.73) 1918.56,1392.75 U5.16@1918.56,1369.25
  SIGNAL1 w10: v3(1762.39,3080.35) 1736.28,3080.35 1634.06,2978.13 1634.06,2830.49 1616.29,2812.72 1616.29,2673.48 1666.85,2622.91 1805.74,2622.91 1834.93,2652.11 1834.98,2652.06 v3(1869.67,2652.06) 1870.08,2651.65 1870.08,2632.5 1886.67,2615.91 1886.67,2581.52 1851.76,2546.62 1851.76,2278.73 1841.71,2268.67 v3(1826.01,2268.67) 1727.33,2268.67 1616.86,2158.2 1616.86,1865.64 1660.78,1821.72 1833.89,1821.72 v3(1866.73,1854.56) 1879.16,1854.56 1889.76,1843.96 1889.76,1824.01 1904.64,1809.13 1904.64,1743.49 1882.32,1721.17 1882.32,1530.47 v3(1831.58,1479.73) 1722.01,1479.73 1616.86,1374.58 1616.86,1075.73 1649.33,1043.25 1849.91,1043.25 v3(1872.28,1065.62)
  SIGNAL2 w10: EN1.1@1151.9,3788.05 1151.9,3686 1258.91,3578.99 1449.23,3578.99 1626.95,3401.26 1626.95,3130.27 1676.87,3080.35 v3(1762.39,3080.35)
  Bottom Layer 1 w10: v3(1866.73,1854.56) 1889.87,1877.7 1889.87,1892.65 1913.01,1915.78 U7.16@1913.01,1931.81 ; v3(1869.67,2652.06) 1915.94,2698.34 U6.16@1915.94,2729.31 ; v3(1872.28,1065.62) 1895.42,1088.76 1895.42,1099.87 1918.56,1123.01 U8.16@1918.56,1142.87
FLTBAR: FLTBAR1.1 J1.3 R16.1 U3.13 U4.13 U5.13 U6.13 U7.13 U8.13 | length 5679.4
  Top Layer 1 w10: R16.1@1907.91,3104.6 1907.91,3088.62 v3(1899.64,3080.35) 1975,3005 U3.13@1975,2955.69 ; v3@1960.25,2222.98 1972.05,2211.18 U4.13@1972.05,2158.19 ; v3@1965.8,1434.04 1977.6,1422.24 U5.13@1977.61,1369.25
  SIGNAL1 w10: J1.3@1948.02,3790.57 1948.02,3347.62 1907.79,3307.39 1907.79,3173.18 1899.64,3165.03 v3(1899.64,3080.35) 2041.01,2938.98 2041.01,2732.1 2005.17,2696.26 1992.42,2696.26 1961.02,2664.86 v3(1961.02,2651.81)
  SIGNAL2 w10: FLTBAR1.1@851.45,3788.53 945.05,3882.12 1856.47,3882.12 J1.3@1948.02,3790.57 ; v3(1872.28,986.88) 1895.48,1010.08 1895.48,1095.31 1919.73,1119.56 2025.98,1119.56 2042.63,1136.22 2042.63,1357.01 v3(1965.61,1434.04) 1957.43,1434.04 1949.78,1426.38 1912.25,1426.38 1892.45,1446.18 1892.45,1750.11 v3(1866.73,1775.82) 1892.16,1801.25 1892.16,1897.25 1912.68,1917.77 2009.89,1917.77 2037.26,1945.14 2037.26,2162.26 1976.54,2222.98 v3(1960.06,2222.98) 1952.4,2215.32 1912.25,2215.32 1892.45,2235.13 1892.45,2333.3 1754.65,2471.09 1754.65,2595.62 1831.24,2672.21 1877.81,2672.21 1920.59,2629.44 1938.97,2629.44 1961.02,2651.49 v3(1961.02,2651.81)
  Bottom Layer 1 w10: v3(1866.73,1775.82) 1884.24,1775.82 1955.32,1846.9 1955.32,1894.8 1972.06,1911.54 U7.13@1972.06,1931.81 ; v3(1872.28,986.88) 1902.23,986.88 1939.93,1024.58 1939.93,1058.68 1960.87,1079.61 1960.87,1102.96 1977.61,1119.71 U8.13@1977.62,1142.87 ; v3(1961.02,2651.81) 1961.22,2651.81 1975,2665.59 U6.13@1975,2729.31
IMON: IMON1.1 R10.2 U3.2 U4.2 U5.2 U6.2 U7.2 U8.2 | length 4151.8
  Top Layer 1 w10: R10.2@1901.67,2577.85 1901.67,2624.18 v3(1928.76,2651.27) 1977.95,2700.46 U3.2@1977.95,2729.31 ; v3(1934.93,1855.91) 1942.91,1855.91 1975,1888 U4.2@1975,1931.81 ; U5.2@1980.57,1142.87 1980.57,1106.27 v3(1989.62,1097.22)
  SIGNAL1 w10: v3(1928.76,2651.27) 1928.76,2289.76 v3(1976.39,2242.13) 1992.09,2226.43 1992.09,2177.4 2036.85,2132.63 2036.85,1930.43 1992.29,1885.86 1974.24,1885.86 1944.29,1855.91 v3(1934.93,1855.91) 1934.93,1843.88 1967.38,1811.43 1967.38,1467.75 v3(1981.94,1453.18) 1997.64,1437.49 1997.64,1387.87 2044.39,1341.12 2044.39,1124.17 2017.43,1097.22 v3(1989.62,1097.22)
  SIGNAL2 w10: v3(1928.76,2651.27) 1965.48,2687.98 2018.26,2687.98 2042.76,2712.49 2042.76,2937.38 1941.2,3038.94 v3(1941.2,3080.95) 1941.2,3124.29 2010.63,3193.72 2010.63,3353.39 2312.98,3655.75 2312.98,3823.07 2367.36,3877.45 2482.79,3877.45 IMON1.1@2573.68,3786.56
  Bottom Layer 1 w10: v3(1941.2,3080.95) 1977.95,3044.2 U6.2@1977.95,2955.69 ; U7.2@1975.02,2158.19 1975.02,2211.07 1979.06,2215.11 1979.06,2230.85 1976.39,2233.51 v3(1976.39,2242.13) ; U8.2@1980.57,1369.24 1980.57,1422.12 1984.61,1426.17 1984.61,1441.91 1981.94,1444.57 v3(1981.94,1453.18)
IREF: IREF1.1 R3.2 U3.3 U4.3 U5.3 U6.3 U7.3 U8.3 | length 4516.4
  Top Layer 1 w10: R3.2@1953.35,2577.85 v3(1953.35,2612.44) 1983.73,2642.82 1983.73,2681.96 1997.64,2695.87 U3.3@1997.64,2729.31 ; v3(1975.1,1854.32) 1994.68,1873.91 U4.3@1994.68,1931.81 ; U5.3@2000.25,1142.87 2000.25,1115.54 2012.66,1103.13 v3(2012.66,1062.97)
  SIGNAL2 w10: v3(2012.66,1062.97) 2012.66,1082.2 2059.63,1129.18 2059.63,1420.29 v3(2021.83,1458.09) 2005.63,1474.29 1973.64,1474.29 1942.74,1443.38 1919.29,1443.38 1909.45,1453.22 1909.45,1890.01 1920.22,1900.77 1950.75,1900.77 1975.1,1876.42 1975.1,1859.32 1975.1,1834.51 1989.93,1819.68 2023.59,1819.68 2054.34,1850.43 2054.34,2208.97 v3(2016.28,2247.04) 1999.97,2247.04 1983.22,2263.78 1970.47,2263.78 1939.02,2232.32 1919.29,2232.32 1909.45,2242.17 1909.45,2341.97 1771.65,2479.76 1771.65,2588.58 1822,2638.93 1846.22,2638.93 1872.72,2612.44 v3(1953.35,2612.44) 1973.17,2632.27 2026.44,2632.27 2059.76,2665.59 2059.76,2947.78 1988.19,3019.35 1988.19,3049.93 v3(2019.21,3080.95) 2019.21,3125.8 2048.52,3155.11 2071.83,3155.11 2097.5,3180.77 2097.5,3356.89 2398.53,3657.92 IREF1.1@2398.53,3786.57
  Bottom Layer 1 w10: U7.3@1994.7,2158.19 1994.7,2206.71 1996.06,2208.07 1996.06,2226.82 v3(2016.28,2247.04) ; U6.3@1997.64,2955.69 1997.64,3059.38 v3(2019.21,3080.95) ; U8.3@2000.25,1369.24 2000.25,1417.77 2001.61,1419.12 2001.61,1437.87 v3(2021.83,1458.09)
